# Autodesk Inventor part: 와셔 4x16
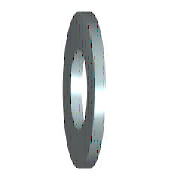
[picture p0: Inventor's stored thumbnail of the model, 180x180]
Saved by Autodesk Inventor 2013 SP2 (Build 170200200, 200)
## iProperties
IsCustomPart: 1
Created: 2012-02
Part Number: 와셔 4x16
Material: 강철, 연강
Description: 미터법 평면 와셔
Document SubType Name: Modeling
Standard: ANSI B18.22M
Designer: mduedu
Standard Revision: 1999
Standards Organization: ANSI
Language: ko-KR
Size Designation: 4 W
Categories: <MemberInstance><Categories><Category DisplayName="조임쇠" InternalName="e4da775c-781d-43d5-af7c-5136215cf5a6" Mnemonic="FSTN"><Category DisplayName="와셔" InternalN
Density: 7.86 g/cm^3
Mass: 3.32115 g
Surface Area: 5.16996 cm^2
Volume: 0.422539 cm^3
Author: mduedu
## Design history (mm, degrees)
sketch "스케치"
  geometry: C1 r 8 at (0, 0); C2 r 2.35 at (0, 0); 1 further point
  constraints: 2 centre point, 2 coincident
  dimensions: "d0" = 4.7 diameter of C2 (= SD1); "d1" = 16 diameter of C1 (= SD2)
extrude "본체" new body sketch "스케치" distance "d2" = 2.3 (= SD); taper "d3" = 0 deg
workaxis "Work Axis1"
workplane "Work Plane1"
body "Solid1"
other parameters: "SD1" = 4.7 [user parameter; used in 1 equation term], "SD2" = 16 [user parameter; used in 1 equation term], "SD" = 2.3 [user parameter; used in 1 equation term], "d4" = 0, "d5" = 0, "d6" = 0, "d7" = 0, "NND" = 4 [user parameter]
